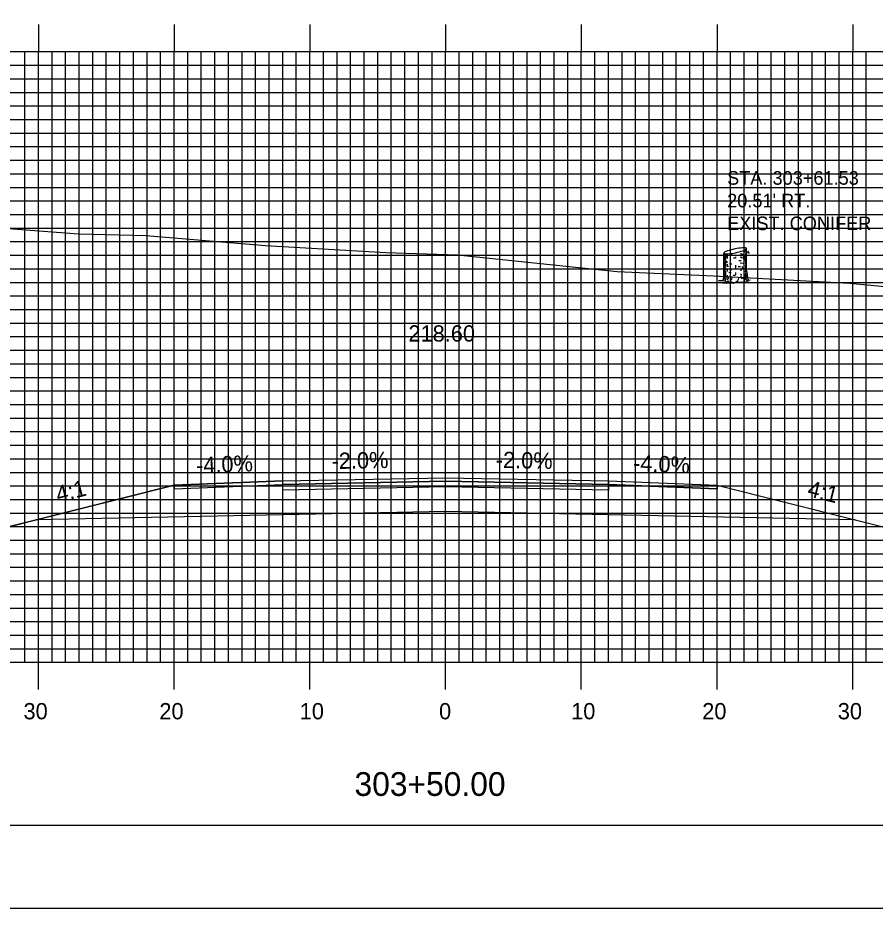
# Model space of a CAD drawing. Extents: x 1816489 to 1816833, y 442591 to 442811.
# Drawn here: x 1816623.6 to 1816686.7, y 442590.5 to 442656.2 of the extents above; entities that cross this region are included whole.
import ezdxf

# ---------------------------------------------------------------- set-up
doc = ezdxf.new("R2010")
doc.units = 0
for name, color, linetype in [('ANNOTATION', 7, 'Continuous'), ('BORDER', 7, 'Continuous'), ('D_Roadway_Centerline', 7, 'Continuous'), ('D_Roadway_Centerline_Text', 7, 'Continuous'), ('D_Roadway_Edge_Shoulder', 7, 'Continuous'), ('D_Roadway_Edge_TW', 7, 'Continuous'), ('D_Roadway_Pavement', 7, 'Continuous'), ('D_Roadway_SlopeLines', 7, 'Continuous'), ('D_Roadway_SubGrade', 7, 'Continuous'), ('D_Text_Monospaced', 7, 'Continuous'), ('H_V ANNOTATION', 7, 'Continuous'), ('M_Trees_Conifer_Pay', 7, 'Continuous'), ('MAJOR', 7, 'Continuous'), ('MINOR', 7, 'Continuous'), ('PLOT BOUNDARY', 7, 'Continuous'), ('S_Roadway_Centerline', 7, 'Continuous')]:
    doc.layers.add(name, color=color, linetype=linetype)

msp = doc.modelspace()

# ---------------------------------------------------------------- linework, layer by layer
at = {"layer": 'BORDER'}
msp.add_lwpolyline([(1816505.473, 442596.665), (1816825.473, 442596.665), (1816825.473, 442806.665), (1816505.473, 442806.665)], close=True, dxfattribs=at)
at = {"layer": 'D_Roadway_Centerline'}
msp.add_lwpolyline([(1816567.648, 442643.659), (1816568.898, 442643.529), (1816570.148, 442643.258), (1816571.398, 442642.845), (1816572.648, 442642.291), (1816620.899, 442618.166), (1816624.899, 442619.166), (1816635.073, 442621.709), (1816643.073, 442622.029), (1816655.073, 442622.269), (1816667.073, 442622.029), (1816675.073, 442621.709), (1816685.247, 442619.166), (1816689.247, 442618.166), (1816717.052, 442632.068), (1816718.302, 442632.599), (1816719.552, 442632.941), (1816720.802, 442633.095), (1816722.052, 442633.061)], dxfattribs=at)
at = {"layer": 'D_Roadway_Edge_Shoulder'}
for points in [[(1816643.073, 442622.029), (1816635.073, 442621.709), (1816635.073, 442621.459), (1816643.073, 442621.779)], [(1816667.073, 442622.029), (1816675.073, 442621.709), (1816675.073, 442621.459), (1816667.073, 442621.779)]]:
    msp.add_lwpolyline(points, close=True, dxfattribs=at)
at = {"layer": 'D_Roadway_Edge_TW'}
msp.add_lwpolyline([(1816643.073, 442621.779), (1816643.073, 442622.029), (1816655.073, 442622.269), (1816667.073, 442622.029), (1816667.073, 442621.779), (1816655.073, 442622.019)], close=True, dxfattribs=at)
at = {"layer": 'D_Roadway_Pavement'}
msp.add_lwpolyline([(1816643.073, 442621.362), (1816643.073, 442621.779), (1816655.073, 442622.019), (1816667.073, 442621.779), (1816667.073, 442621.362), (1816655.073, 442621.602)], close=True, dxfattribs=at)
at = {"layer": 'D_Roadway_SlopeLines'}
for points in [[(1816635.073, 442621.709), (1816620.899, 442618.166)], [(1816675.073, 442621.709), (1816689.247, 442618.166)]]:
    msp.add_lwpolyline(points, dxfattribs=at)
at = {"layer": 'D_Roadway_SubGrade'}
msp.add_lwpolyline([(1816643.073, 442619.529), (1816624.899, 442619.166), (1816635.073, 442621.709), (1816635.073, 442621.459), (1816643.073, 442621.779), (1816655.073, 442622.019), (1816667.073, 442621.779), (1816675.073, 442621.459), (1816675.073, 442621.709), (1816685.247, 442619.166), (1816667.073, 442619.529), (1816655.073, 442619.769)], close=True, dxfattribs=at)
at = {"layer": 'M_Trees_Conifer_Pay'}
for p, q in [((1816675.584, 442637.098), (1816675.584, 442638.82)), ((1816675.631, 442638.782), (1816675.631, 442638.311)), ((1816675.69, 442638.771), (1816675.69, 442638.673)), ((1816675.815, 442638.763), (1816675.815, 442638.531)), ((1816676.035, 442638.784), (1816676.035, 442638.616)), ((1816676.831, 442638.826), (1816676.831, 442638.626)), ((1816677.059, 442639.022), (1816677.059, 442638.799)), ((1816677.059, 442638.71), (1816677.059, 442638.663)), ((1816677.176, 442639.083), (1816677.176, 442638.92)), ((1816677.176, 442638.852), (1816677.176, 442638.725)), ((1816677.248, 442637.508), (1816677.248, 442639.155)), ((1816675.631, 442638.247), (1816675.631, 442637.938)), ((1816675.69, 442638.599), (1816675.69, 442638.395)), ((1816675.69, 442638.337), (1816675.69, 442638.138)), ((1816675.69, 442638.091), (1816675.69, 442637.755)), ((1816675.815, 442638.49), (1816675.815, 442638.416)), ((1816675.815, 442638.013), (1816675.815, 442637.874)), ((1816676.035, 442638.379), (1816676.035, 442638.142)), ((1816676.44, 442638.552), (1816676.44, 442638.457)), ((1816676.831, 442638.568), (1816676.831, 442638.48)), ((1816676.831, 442638.132), (1816676.831, 442638.027)), ((1816677.059, 442638.328), (1816677.059, 442638.196)), ((1816677.059, 442638.085), (1816677.059, 442637.975)), ((1816677.116, 442638.527), (1816677.065, 442638.467)), ((1816677.176, 442638.538), (1816677.176, 442638.202)), ((1816677.176, 442638.165), (1816677.176, 442638.002)), ((1816675.631, 442637.891), (1816675.631, 442637.399)), ((1816675.631, 442637.345), (1816675.631, 442637.098)), ((1816675.69, 442637.702), (1816675.69, 442637.566)), ((1816675.69, 442637.467), (1816675.69, 442637.088)), ((1816675.815, 442637.602), (1816675.815, 442637.461)), ((1816676.035, 442637.897), (1816676.035, 442637.745)), ((1816676.035, 442637.702), (1816676.035, 442637.528)), ((1816676.44, 442637.938), (1816676.44, 442637.864)), ((1816676.44, 442637.839), (1816676.44, 442637.691)), ((1816676.44, 442637.399), (1816676.44, 442637.246)), ((1816676.831, 442637.66), (1816676.831, 442637.514)), ((1816677.059, 442637.839), (1816677.059, 442637.698)), ((1816677.059, 442637.471), (1816677.059, 442637.298)), ((1816677.176, 442637.955), (1816677.176, 442637.738)), ((1816677.176, 442637.707), (1816677.176, 442637.633)), ((1816677.176, 442637.593), (1816677.176, 442637.419)), ((1816675.815, 442637.199), (1816675.815, 442637.104)), ((1816675.815, 442636.705), (1816675.978, 442636.768)), ((1816676.035, 442637.251), (1816676.035, 442637.098)), ((1816676.252, 442636.641), (1816676.126, 442636.705)), ((1816676.831, 442637.282), (1816676.831, 442637.193))]:
    msp.add_line(p, q, dxfattribs=at)
for points in [[(1816677.065, 442638.653), (1816677.102, 442638.579), (1816677.149, 442638.636), (1816677.207, 442638.704), (1816677.299, 442638.898), (1816677.363, 442638.945), (1816677.394, 442638.952)], [(1816677.079, 442638.4), (1816677.116, 442638.527), (1816677.18, 442638.643), (1816677.211, 442638.71), (1816677.279, 442638.856)], [(1816677.294, 442638.886), (1816677.369, 442638.894), (1816677.441, 442638.795)], [(1816675.763, 442638.125), (1816675.757, 442638.221), (1816675.8, 442638.198), (1816675.8, 442638.103)], [(1816677.031, 442638.616), (1816677.001, 442638.531), (1816676.997, 442638.463), (1816677.027, 442638.4)], [(1816677.248, 442637.508), (1816677.299, 442637.246), (1816677.316, 442636.973), (1816677.373, 442636.847), (1816677.509, 442636.816), (1816677.279, 442636.779), (1816677.279, 442636.779), (1816677.285, 442636.732), (1816677.532, 442636.637), (1816677.258, 442636.654), (1816676.902, 442636.674), (1816676.581, 442636.664), (1816676.587, 442636.746), (1816676.439, 442636.664), (1816676.252, 442636.641), (1816676.276, 442636.573), (1816676.008, 442636.616), (1816675.788, 442636.589), (1816675.495, 442636.606), (1816675.784, 442636.664), (1816675.815, 442636.705), (1816675.652, 442636.763), (1816675.415, 442636.773), (1816675.174, 442636.773), (1816675.516, 442636.831), (1816675.558, 442636.911), (1816675.584, 442637.098)], [(1816676.902, 442637.726), (1816676.915, 442637.65), (1816676.962, 442637.66), (1816676.949, 442637.827)], [(1816677.174, 442637.366), (1816677.18, 442637.22), (1816677.227, 442637.152), (1816677.237, 442636.952)], [(1816675.632, 442637.051), (1816675.611, 442636.973), (1816675.59, 442636.878)], [(1816675.71, 442637.03), (1816675.716, 442636.915), (1816675.663, 442636.826), (1816675.652, 442636.763)], [(1816675.873, 442637.057), (1816675.873, 442636.925), (1816675.784, 442636.826)], [(1816676.099, 442636.816), (1816676.167, 442636.911), (1816676.193, 442637.051)], [(1816676.587, 442636.746), (1816676.661, 442636.888), (1816676.671, 442636.989)], [(1816676.838, 442637.115), (1816676.848, 442636.989), (1816676.922, 442636.946)], [(1816677.116, 442636.726), (1816677.102, 442636.864), (1816677.027, 442636.993)], [(1816677.075, 442637.22), (1816677.149, 442637.115), (1816677.153, 442636.942), (1816677.279, 442636.779)]]:
    msp.add_lwpolyline(points, dxfattribs=at)
for centre, radius, start, end in [((1816675.616, 442638.641), 0.0334, 163.94846, 180), ((1816675.615, 442638.818), 0.0314, 156.51582, 169.2194), ((1816675.61, 442638.819), 0.0264, 169.2194, 180.03145), ((1816675.607, 442638.819), 0.0226, 180.03145, 191.7194), ((1816675.607, 442638.819), 0.0226, 191.7194, 203.40735), ((1816675.61, 442638.821), 0.0264, 203.40735, 214.2194), ((1816675.635, 442638.81), 0.0527, 146.7194, 156.51582), ((1816675.614, 442638.824), 0.0314, 214.2194, 226.92298), ((1816675.659, 442638.794), 0.0817, 132.38868, 146.7194), ((1816675.629, 442638.839), 0.0527, 226.92298, 236.7194), ((1816675.645, 442638.863), 0.0817, 236.7194, 251.05013), ((1816675.773, 442638.669), 0.251, 124.2194, 132.38868), ((1816675.7, 442639.023), 0.251, 251.05013, 259.2194), ((1816676.083, 442638.214), 0.802, 108.05939, 124.2194), ((1816675.803, 442639.564), 0.802, 259.2194, 275.37941), ((1816677.44, 442634.052), 5.179, 101.7194, 108.05939), ((1816675.392, 442643.922), 5.179, 275.37941, 281.7194), ((1816676.416, 442642.832), 4.124, 264.6955, 266.73309), ((1816677.44, 442634.052), 5.179, 95.37941, 101.7194), ((1816675.392, 442643.922), 5.179, 281.7194, 288.05939), ((1816676.416, 442642.832), 4.124, 276.23804, 278.1032), ((1816677.029, 442638.41), 0.802, 79.2194, 95.37941), ((1816676.917, 442639.314), 0.571, 278.1032, 284.36665), ((1816676.749, 442639.761), 0.802, 288.05939, 304.2194), ((1816676.917, 442639.469), 0.571, 284.43166, 292.41325), ((1816676.917, 442639.314), 0.571, 297.0237, 300), ((1816677.132, 442638.951), 0.251, 71.05013, 79.2194), ((1816677.059, 442639.305), 0.251, 304.2194, 312.38868), ((1816677.116, 442639.123), 0.172, 300, 311.25059), ((1816677.116, 442638.969), 0.172, 300, 311.25059), ((1816677.187, 442639.111), 0.0817, 56.7194, 71.05013), ((1816677.173, 442639.181), 0.0817, 312.38868, 326.7194), ((1816677.189, 442639.041), 0.0624, 311.25059, 330), ((1816677.189, 442638.886), 0.0624, 311.25059, 330), ((1816677.203, 442639.135), 0.0527, 46.92298, 56.7194), ((1816677.218, 442639.151), 0.0314, 34.2194, 46.92298), ((1816677.197, 442639.165), 0.0527, 326.7194, 336.51582), ((1816677.204, 442639.032), 0.0441, 330, 343.94846), ((1816677.204, 442638.877), 0.0441, 330, 343.94846), ((1816677.222, 442639.154), 0.0264, 23.40735, 34.2194), ((1816677.217, 442639.156), 0.0314, 336.51582, 349.2194), ((1816677.225, 442639.155), 0.0226, 11.7194, 23.40735), ((1816677.215, 442639.029), 0.0334, 343.94846, 354.21506), ((1816677.215, 442638.874), 0.0334, 343.94846, 354.21506), ((1816677.225, 442639.155), 0.0226, 0.03145, 11.7194), ((1816677.222, 442639.155), 0.0264, 349.2194, 0.03145), ((1816675.616, 442638.641), 0.0334, 180, 196.05154), ((1816675.616, 442638.195), 0.0334, 163.94846, 180), ((1816675.616, 442638.195), 0.0334, 180, 196.05154), ((1816675.616, 442637.985), 0.0334, 163.94846, 180), ((1816675.626, 442638.644), 0.0441, 196.05154, 210), ((1816675.626, 442638.198), 0.0441, 196.05154, 210), ((1816675.642, 442638.654), 0.0624, 210, 228.74941), ((1816675.642, 442638.207), 0.0624, 210, 228.74941), ((1816675.715, 442638.736), 0.172, 228.74941, 240), ((1816675.715, 442638.289), 0.172, 228.74941, 240), ((1816675.914, 442639.081), 0.571, 240, 240.33672), ((1816675.914, 442638.634), 0.571, 240, 240.33672), ((1816675.915, 442638.87), 0.571, 240, 247.05866), ((1816675.914, 442639.081), 0.571, 246.85973, 257.98457), ((1816676.415, 442642.152), 4.124, 264.08098, 266.66759), ((1816676.415, 442642.599), 4.124, 268.07512, 270), ((1816676.415, 442642.599), 4.124, 270, 270.35814), ((1816676.416, 442642.388), 4.124, 273.70524, 275.95043), ((1816676.415, 442642.599), 4.124, 275.78493, 277.05584), ((1816676.415, 442642.152), 4.124, 277.61247, 278.1032), ((1816676.916, 442638.634), 0.571, 278.1032, 286.92962), ((1816676.917, 442638.87), 0.571, 284.44928, 297.04285), ((1816676.916, 442638.634), 0.571, 297.18959, 300), ((1816677.115, 442638.289), 0.172, 300, 311.25059), ((1816677.187, 442638.207), 0.0624, 311.25059, 330), ((1816677.203, 442638.198), 0.0441, 330, 343.94846), ((1816677.213, 442638.195), 0.0334, 343.94846, 354.21506), ((1816677.215, 442638.43), 0.0334, 343.94846, 354.21506), ((1816675.616, 442637.985), 0.0334, 180, 196.05154), ((1816675.616, 442637.748), 0.0334, 163.94846, 180), ((1816675.616, 442637.748), 0.0334, 180, 196.05154), ((1816675.616, 442637.55), 0.0334, 163.94846, 180), ((1816675.616, 442637.355), 0.0334, 163.94846, 180), ((1816675.616, 442637.355), 0.0334, 180, 196.05154), ((1816675.626, 442637.988), 0.0441, 196.05154, 210), ((1816675.626, 442637.751), 0.0441, 196.05154, 210), ((1816675.626, 442637.358), 0.0441, 196.05154, 210), ((1816675.642, 442637.997), 0.0624, 210, 228.74941), ((1816675.642, 442637.76), 0.0624, 210, 228.74941), ((1816675.642, 442637.367), 0.0624, 210, 228.74941), ((1816675.715, 442638.079), 0.172, 228.74941, 240), ((1816675.715, 442637.843), 0.172, 228.74941, 240), ((1816675.914, 442638.424), 0.571, 240, 246.85973), ((1816675.914, 442638.188), 0.571, 240, 246.85973), ((1816675.903, 442637.996), 0.571, 241.23686, 248.02677), ((1816675.914, 442638.424), 0.571, 259.27072, 261.8968), ((1816676.415, 442641.942), 4.124, 261.8968, 263.14738), ((1816676.415, 442641.507), 4.124, 263.49906, 265.83975), ((1816676.415, 442641.705), 4.124, 264.71603, 266.31934), ((1816676.415, 442641.942), 4.124, 270, 270.35814), ((1816676.415, 442641.942), 4.124, 273.14934, 275.45691), ((1816676.916, 442638.188), 0.571, 285.39827, 297.18959), ((1816676.916, 442637.99), 0.571, 289.29072, 300), ((1816676.916, 442638.424), 0.571, 297.18959, 300), ((1816677.115, 442638.079), 0.172, 300, 311.25059), ((1816677.115, 442637.645), 0.172, 300, 311.25059), ((1816677.187, 442637.997), 0.0624, 311.25059, 330), ((1816677.187, 442637.562), 0.0624, 311.25059, 330), ((1816677.203, 442637.988), 0.0441, 330, 343.94846), ((1816677.203, 442637.553), 0.0441, 330, 343.94846), ((1816677.213, 442637.985), 0.0334, 343.94846, 354.21506), ((1816677.213, 442637.55), 0.0334, 343.94846, 354.21506), ((1816675.616, 442637.134), 0.0334, 163.94846, 180), ((1816675.616, 442637.134), 0.0334, 180, 196.05154), ((1816675.626, 442637.137), 0.0441, 196.05154, 210), ((1816675.642, 442637.146), 0.0624, 210, 228.74941), ((1816675.715, 442637.449), 0.172, 228.74941, 240), ((1816675.715, 442637.229), 0.172, 228.74941, 240), ((1816675.914, 442637.794), 0.571, 240, 246.85973), ((1816675.914, 442637.574), 0.571, 240, 244.53138), ((1816676.415, 442641.092), 4.124, 262.44379, 263.51202), ((1816676.415, 442641.312), 4.124, 267.81166, 270), ((1816676.415, 442641.312), 4.124, 270, 270.13279), ((1816676.415, 442641.312), 4.124, 275.78493, 276.78961), ((1816676.415, 442641.092), 4.124, 277.36842, 278.1032), ((1816676.916, 442637.574), 0.571, 278.1032, 281.63703), ((1816676.916, 442637.794), 0.571, 288.50673, 297.27208), ((1816677.115, 442637.229), 0.172, 300, 311.25059), ((1816677.187, 442637.146), 0.0624, 311.25059, 330), ((1816677.203, 442637.137), 0.0441, 330, 343.94846), ((1816677.213, 442637.134), 0.0334, 343.94846, 354.21506)]:
    msp.add_arc(centre, radius, start, end, dxfattribs=at)
at = {"layer": 'MAJOR'}
for p, q in [((1816625.073, 442655.669), (1816625.073, 442653.665)), ((1816635.073, 442655.669), (1816635.073, 442653.665)), ((1816645.073, 442655.669), (1816645.073, 442653.665)), ((1816655.073, 442655.669), (1816655.073, 442653.665)), ((1816665.073, 442655.669), (1816665.073, 442653.665)), ((1816675.073, 442655.669), (1816675.073, 442653.665)), ((1816685.073, 442655.669), (1816685.073, 442653.665)), ((1816515.073, 442653.665), (1816795.073, 442653.665)), ((1816515.073, 442653.665), (1816795.073, 442653.665)), ((1816625.073, 442608.665), (1816625.073, 442653.665)), ((1816635.073, 442608.665), (1816635.073, 442653.665)), ((1816645.073, 442608.665), (1816645.073, 442653.665)), ((1816655.073, 442608.665), (1816655.073, 442653.665)), ((1816665.073, 442608.665), (1816665.073, 442653.665)), ((1816675.073, 442608.665), (1816675.073, 442653.665)), ((1816685.073, 442608.665), (1816685.073, 442653.665)), ((1816515.073, 442648.665), (1816795.073, 442648.665)), ((1816515.073, 442643.665), (1816795.073, 442643.665)), ((1816515.073, 442638.665), (1816795.073, 442638.665)), ((1816515.073, 442633.665), (1816795.073, 442633.665)), ((1816515.073, 442628.665), (1816795.073, 442628.665)), ((1816515.073, 442623.665), (1816795.073, 442623.665)), ((1816515.073, 442618.665), (1816795.073, 442618.665)), ((1816515.073, 442613.665), (1816795.073, 442613.665)), ((1816515.073, 442608.665), (1816795.073, 442608.665)), ((1816515.073, 442608.665), (1816795.073, 442608.665)), ((1816625.073, 442606.661), (1816625.073, 442608.665)), ((1816635.073, 442606.661), (1816635.073, 442608.665)), ((1816645.073, 442606.661), (1816645.073, 442608.665)), ((1816655.073, 442606.661), (1816655.073, 442608.665)), ((1816665.073, 442606.661), (1816665.073, 442608.665)), ((1816675.073, 442606.661), (1816675.073, 442608.665)), ((1816685.073, 442606.661), (1816685.073, 442608.665))]:
    msp.add_line(p, q, dxfattribs=at)
at = {"layer": 'MINOR'}
for p, q in [((1816624.073, 442608.665), (1816624.073, 442653.665)), ((1816626.073, 442608.665), (1816626.073, 442653.665)), ((1816627.073, 442608.665), (1816627.073, 442653.665)), ((1816628.073, 442608.665), (1816628.073, 442653.665)), ((1816629.073, 442608.665), (1816629.073, 442653.665)), ((1816630.073, 442608.665), (1816630.073, 442653.665)), ((1816631.073, 442608.665), (1816631.073, 442653.665)), ((1816632.073, 442608.665), (1816632.073, 442653.665)), ((1816633.073, 442608.665), (1816633.073, 442653.665)), ((1816634.073, 442608.665), (1816634.073, 442653.665)), ((1816636.073, 442608.665), (1816636.073, 442653.665)), ((1816637.073, 442608.665), (1816637.073, 442653.665)), ((1816638.073, 442608.665), (1816638.073, 442653.665)), ((1816639.073, 442608.665), (1816639.073, 442653.665)), ((1816640.073, 442608.665), (1816640.073, 442653.665)), ((1816641.073, 442608.665), (1816641.073, 442653.665)), ((1816642.073, 442608.665), (1816642.073, 442653.665)), ((1816643.073, 442608.665), (1816643.073, 442653.665)), ((1816644.073, 442608.665), (1816644.073, 442653.665)), ((1816646.073, 442608.665), (1816646.073, 442653.665)), ((1816647.073, 442608.665), (1816647.073, 442653.665)), ((1816648.073, 442608.665), (1816648.073, 442653.665)), ((1816649.073, 442608.665), (1816649.073, 442653.665)), ((1816650.073, 442608.665), (1816650.073, 442653.665)), ((1816651.073, 442608.665), (1816651.073, 442653.665)), ((1816652.073, 442608.665), (1816652.073, 442653.665)), ((1816653.073, 442608.665), (1816653.073, 442653.665)), ((1816654.073, 442608.665), (1816654.073, 442653.665)), ((1816656.073, 442608.665), (1816656.073, 442653.665)), ((1816657.073, 442608.665), (1816657.073, 442653.665)), ((1816658.073, 442608.665), (1816658.073, 442653.665)), ((1816659.073, 442608.665), (1816659.073, 442653.665)), ((1816660.073, 442608.665), (1816660.073, 442653.665)), ((1816661.073, 442608.665), (1816661.073, 442653.665)), ((1816662.073, 442608.665), (1816662.073, 442653.665)), ((1816663.073, 442608.665), (1816663.073, 442653.665)), ((1816664.073, 442608.665), (1816664.073, 442653.665)), ((1816666.073, 442608.665), (1816666.073, 442653.665)), ((1816667.073, 442608.665), (1816667.073, 442653.665)), ((1816668.073, 442608.665), (1816668.073, 442653.665)), ((1816669.073, 442608.665), (1816669.073, 442653.665)), ((1816670.073, 442608.665), (1816670.073, 442653.665)), ((1816671.073, 442608.665), (1816671.073, 442653.665)), ((1816672.073, 442608.665), (1816672.073, 442653.665)), ((1816673.073, 442608.665), (1816673.073, 442653.665)), ((1816674.073, 442608.665), (1816674.073, 442653.665)), ((1816676.073, 442608.665), (1816676.073, 442653.665)), ((1816677.073, 442608.665), (1816677.073, 442653.665)), ((1816678.073, 442608.665), (1816678.073, 442653.665)), ((1816679.073, 442608.665), (1816679.073, 442653.665)), ((1816680.073, 442608.665), (1816680.073, 442653.665)), ((1816681.073, 442608.665), (1816681.073, 442653.665)), ((1816682.073, 442608.665), (1816682.073, 442653.665)), ((1816683.073, 442608.665), (1816683.073, 442653.665)), ((1816684.073, 442608.665), (1816684.073, 442653.665)), ((1816686.073, 442608.665), (1816686.073, 442653.665)), ((1816515.073, 442652.665), (1816795.073, 442652.665)), ((1816515.073, 442651.665), (1816795.073, 442651.665)), ((1816515.073, 442650.665), (1816795.073, 442650.665)), ((1816515.073, 442649.665), (1816795.073, 442649.665)), ((1816515.073, 442647.665), (1816795.073, 442647.665)), ((1816515.073, 442646.665), (1816795.073, 442646.665)), ((1816515.073, 442645.665), (1816795.073, 442645.665)), ((1816515.073, 442644.665), (1816795.073, 442644.665)), ((1816515.073, 442642.665), (1816795.073, 442642.665)), ((1816515.073, 442641.665), (1816795.073, 442641.665)), ((1816515.073, 442640.665), (1816795.073, 442640.665)), ((1816515.073, 442639.665), (1816795.073, 442639.665)), ((1816515.073, 442637.665), (1816795.073, 442637.665)), ((1816515.073, 442636.665), (1816795.073, 442636.665)), ((1816515.073, 442635.665), (1816795.073, 442635.665)), ((1816515.073, 442634.665), (1816795.073, 442634.665)), ((1816515.073, 442632.665), (1816795.073, 442632.665)), ((1816515.073, 442631.665), (1816795.073, 442631.665)), ((1816515.073, 442630.665), (1816795.073, 442630.665)), ((1816515.073, 442629.665), (1816795.073, 442629.665)), ((1816515.073, 442627.665), (1816795.073, 442627.665)), ((1816515.073, 442626.665), (1816795.073, 442626.665)), ((1816515.073, 442625.665), (1816795.073, 442625.665)), ((1816515.073, 442624.665), (1816795.073, 442624.665)), ((1816515.073, 442622.665), (1816795.073, 442622.665)), ((1816515.073, 442621.665), (1816795.073, 442621.665)), ((1816515.073, 442620.665), (1816795.073, 442620.665)), ((1816515.073, 442619.665), (1816795.073, 442619.665)), ((1816515.073, 442617.665), (1816795.073, 442617.665)), ((1816515.073, 442616.665), (1816795.073, 442616.665)), ((1816515.073, 442615.665), (1816795.073, 442615.665)), ((1816515.073, 442614.665), (1816795.073, 442614.665)), ((1816515.073, 442612.665), (1816795.073, 442612.665)), ((1816515.073, 442611.665), (1816795.073, 442611.665)), ((1816515.073, 442610.665), (1816795.073, 442610.665)), ((1816515.073, 442609.665), (1816795.073, 442609.665))]:
    msp.add_line(p, q, dxfattribs=at)
at = {"layer": 'PLOT BOUNDARY'}
msp.add_lwpolyline([(1816489.286, 442590.547), (1816829.286, 442590.547), (1816829.286, 442810.547), (1816489.286, 442810.547)], close=True, dxfattribs=at)
at = {"layer": 'S_Roadway_Centerline'}
msp.add_lwpolyline([(1816549.048, 442644.54), (1816573.391, 442643.387), (1816581.615, 442642.85), (1816596.597, 442644.164), (1816598.715, 442644.176), (1816599.937, 442644.148), (1816605.718, 442643.1), (1816614.452, 442641.285), (1816616.076, 442641.146), (1816628.026, 442640.237), (1816632.984, 442640.114), (1816641.806, 442639.39), (1816650.657, 442638.868), (1816655.939, 442638.7), (1816667.72, 442637.466), (1816674.808, 442637.145), (1816684.828, 442636.605), (1816695.528, 442635.592)], dxfattribs=at)

# ---------------------------------------------------------------- texts
at = {"layer": 'ANNOTATION'}
for s, rotation, p in [('-4.0%', 2.29061, (1816636.705, 442622.576)), ('-2.0%', 1.14576, (1816646.679, 442622.902)), ('-2.0%', 358.85424, (1816658.759, 442622.996)), ('-4.0%', 357.70939, (1816668.865, 442622.759)), ('4:1', 14.03624, (1816626.522, 442620.433)), ('4:1', 345.96376, (1816681.666, 442620.922))]:
    msp.add_text(s, height=1.2, rotation=rotation, dxfattribs=at).set_placement(p)
at = {"layer": 'D_Roadway_Centerline'}
for s, p in [('C', (1816655.068, 442622.269)), ('L', (1816655.073, 442622.262))]:
    msp.add_text(s, height=0.0146, dxfattribs=at).set_placement(p)
at = {"layer": 'D_Roadway_Centerline_Text'}
msp.add_text('218.60', height=1.2, dxfattribs=at).set_placement((1816652.333, 442632.299))
at = {"layer": 'D_Text_Monospaced'}
for s, height, p in [('STA. 303+61.53', 0.99996, (1816675.817, 442643.859)), ("20.51' RT.", 1, (1816675.817, 442642.191)), ('EXIST. CONIFER', 0.99996, (1816675.817, 442640.511))]:
    msp.add_text(s, height=height, dxfattribs=at).set_placement(p)
at = {"layer": 'H_V ANNOTATION'}
for s, height, p in [('30', 1.2, (1816623.97, 442604.465)), ('20', 1.2, (1816633.981, 442604.465)), ('10', 1.2, (1816644.324, 442604.465)), ('0', 1.2, (1816654.591, 442604.465)), ('10', 1.2, (1816664.324, 442604.465)), ('20', 1.2, (1816673.981, 442604.465)), ('30', 1.2, (1816683.97, 442604.465)), ('303+50.00', 1.75, (1816648.362, 442598.821))]:
    msp.add_text(s, height=height, dxfattribs=at).set_placement(p)

doc.saveas('drawing.dxf')
